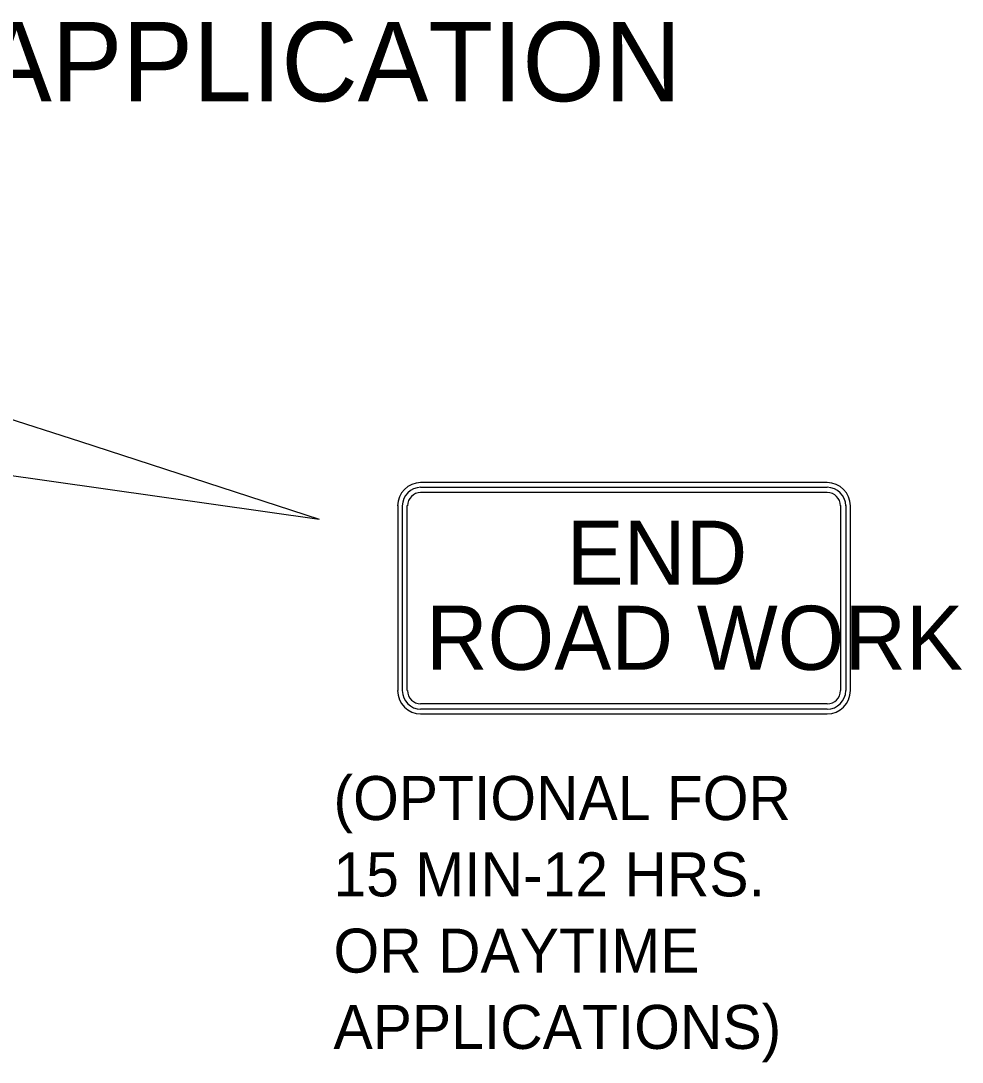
# Model space of a CAD drawing. Extents: x 1531.4 to 1538.58, y 1529.59 to 1539.33.
# Drawn here: x 1535.789 to 1537.074, y 1537.915 to 1539.335 of the extents above; entities that cross this region are included whole.
import ezdxf

# ---------------------------------------------------------------- set-up
doc = ezdxf.new("R2010")
doc.units = 0
for name, color, linetype in [('DETL-DIMS', 7, 'Continuous'), ('DETL-LINE', 7, 'Continuous'), ('DETL-NOTE', 7, 'Continuous'), ('DETL-TITL', 7, 'Continuous')]:
    doc.layers.add(name, color=color, linetype=linetype)

msp = doc.modelspace()

# ---------------------------------------------------------------- linework, layer by layer
at = {"layer": 'DETL-DIMS'}
for p, q in [((1535.362, 1538.9247), (1535.8708, 1538.7611)), ((1534.3772, 1538.9135), (1536.1963, 1538.6552)), ((1535.8708, 1538.7611), (1536.1963, 1538.6552))]:
    msp.add_line(p, q, dxfattribs=at)
at = {"layer": 'DETL-LINE'}
for p, q in [((1536.8896, 1538.7051), (1536.3349, 1538.7051)), ((1536.3349, 1538.6987), (1536.8896, 1538.6987)), ((1536.3349, 1538.692), (1536.8896, 1538.692)), ((1536.3036, 1538.6738), (1536.3036, 1538.4215)), ((1536.31, 1538.4215), (1536.31, 1538.6738)), ((1536.3166, 1538.4215), (1536.3166, 1538.6738)), ((1536.9076, 1538.6738), (1536.9076, 1538.4215)), ((1536.9077, 1538.6736), (1536.9076, 1538.6738)), ((1536.9149, 1538.6738), (1536.9149, 1538.4215)), ((1536.9213, 1538.4215), (1536.9213, 1538.6738)), ((1536.8896, 1538.4035), (1536.3349, 1538.4035)), ((1536.8896, 1538.3963), (1536.3349, 1538.3963)), ((1536.3349, 1538.3899), (1536.8896, 1538.3899))]:
    msp.add_line(p, q, dxfattribs=at)
for centre, radius, start, end in [((1536.3351, 1538.6735), 0.0316, 90, 180), ((1536.3351, 1538.6735), 0.0252, 90, 180), ((1536.8896, 1538.6735), 0.0316, 0, 90), ((1536.8896, 1538.6735), 0.0252, 0, 90), ((1536.3351, 1538.6735), 0.0181, 90, 180), ((1536.8896, 1538.6735), 0.0181, 0, 90), ((1536.3351, 1538.4215), 0.0316, 180, 270), ((1536.3351, 1538.4215), 0.0252, 180, 270), ((1536.3351, 1538.4215), 0.0181, 180, 270), ((1536.8896, 1538.4215), 0.0316, 270, 0), ((1536.8896, 1538.4215), 0.0181, 270, 0), ((1536.8896, 1538.4215), 0.0252, 270, 0)]:
    msp.add_arc(centre, radius, start, end, dxfattribs=at)

# ---------------------------------------------------------------- texts
for s, p in [('END', (1536.534, 1538.5659)), ('ROAD WORK', (1536.342, 1538.4499))]:
    msp.add_text(s, height=0.08731, rotation=360, dxfattribs=at).set_placement(p)
at = {"layer": 'DETL-NOTE'}
for s, p in [('(OPTIONAL FOR', (1536.216, 1538.2451)), ('15 MIN-12 HRS. ', (1536.216, 1538.1411)), ('OR DAYTIME', (1536.216, 1538.0371)), ('APPLICATIONS)', (1536.216, 1537.9331))]:
    msp.add_text(s, height=0.06, dxfattribs=at).set_placement(p)
at = {"layer": 'DETL-TITL'}
msp.add_text('TEMPORARY TRAFFIC CONTROL TYPICAL APPLICATION', height=0.108, dxfattribs=at).set_placement((1532.7424, 1539.225))

doc.saveas('drawing.dxf')
